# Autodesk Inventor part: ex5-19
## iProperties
Created: 2006-03
Part Number: ex5-19
Document SubType Name: Modeling
Designer: Elise Moss
Author: Elise Moss
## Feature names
1. Revolution1
2. Hole1
3. Extrusion1
4. Circular Pattern1
